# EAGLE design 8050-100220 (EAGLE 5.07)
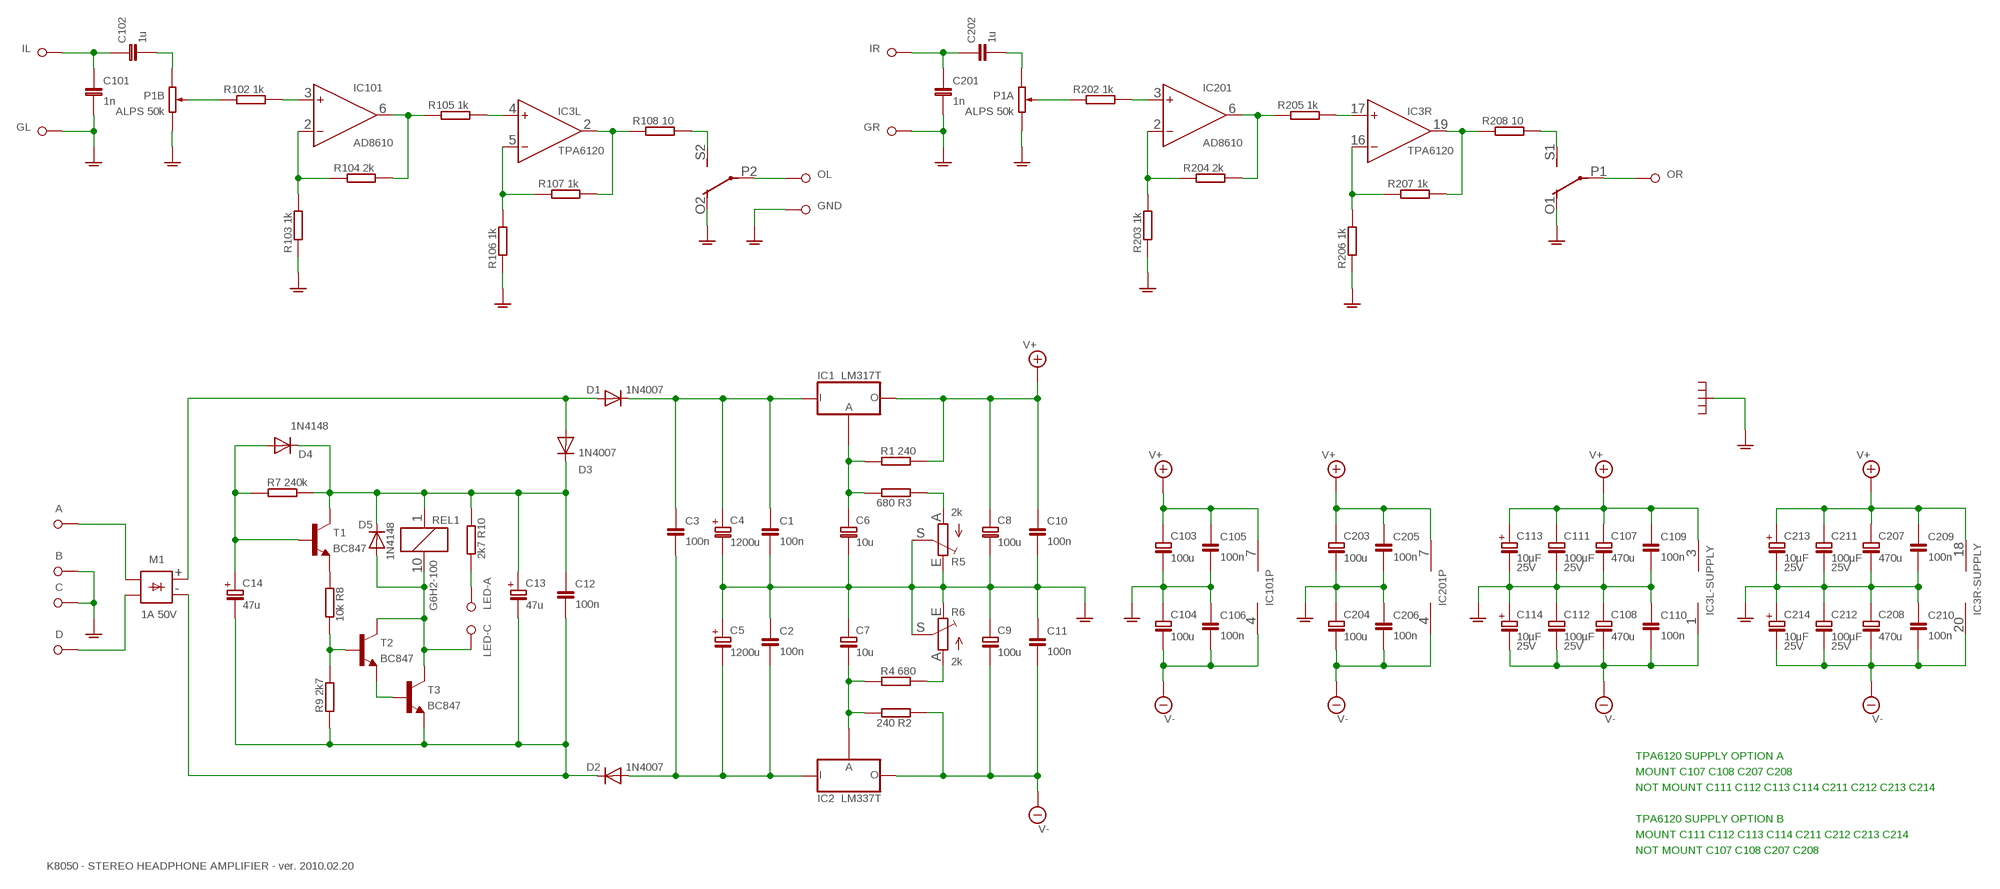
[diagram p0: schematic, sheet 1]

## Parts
A  AC 1  2,15/1,0  [2,15/1,0]
B  AC COM  2,15/1,0  [2,15/1,0]
C  AC COM  2,15/1,0  [2,15/1,0]
C1  100n  C075-042X103  [C075-042X103]
C2  100n  C075-042X103  [C075-042X103]
C3  100n  C075-042X103  [C075-042X103]
C4  1200u  ELECTROLYTIC-FC-E12X30  [E-12-30]
C5  1200u  ELECTROLYTIC-FC-E12X30  [E-12-30]
C6  10u  FM1E470  [E-050-110-020-05]
C7  10u  FM1E470  [E-050-110-020-05]
C8  100u  FM1E101  [E-063-112-025-05]
C9  100u  FM1E101  [E-063-112-025-05]
C10  100n  C075-042X103  [C075-042X103]
C11  100n  C075-042X103  [C075-042X103]
C12  100n  C075-042X103  [C075-042X103]
C13  47u  ELECTROLYTIC-FC-E04X07  [E-04-07]
C14  47u  ELECTROLYTIC-FC-E04X07  [E-04-07]
C101  1n  CC1206  [C1206]
C102  1u  C075-063X106  [C075-063X106]
C103  100u  FM1E101  [E-063-112-025-05]
C104  100u  FM1E101  [E-063-112-025-05]
C105  100n  CC1206  [C1206]
C106  100n  CC1206  [C1206]
C107  470u  FM1E471  [E-100-160-050-06]
C108  470u  FM1E471  [E-100-160-050-06]
C109  100n  CC1206  [C1206]
C110  100n  CC1206  [C1206]
C111  100µF  FM1E101  [E-063-112-025-05]
C112  100µF  FM1E101  [E-063-112-025-05]
C113  10µF  FC1E100  [E-040-070-015-045]
C114  10µF  FC1E100  [E-040-070-015-045]
C201  1n  CC1206  [C1206]
C202  1u  C075-063X106  [C075-063X106]
C203  100u  FM1E101  [E-063-112-025-05]
C204  100u  FM1E101  [E-063-112-025-05]
C205  100n  CC1206  [C1206]
C206  100n  CC1206  [C1206]
C207  470u  FM1E471  [E-100-160-050-06]
C208  470u  FM1E471  [E-100-160-050-06]
C209  100n  CC1206  [C1206]
C210  100n  CC1206  [C1206]
C211  100µF  FM1E101  [E-063-112-025-05]
C212  100µF  FM1E101  [E-063-112-025-05]
C213  10µF  FC1E100  [E-040-070-015-045]
C214  10µF  FC1E100  [E-040-070-015-045]
D  AC 2  2,15/1,0  [2,15/1,0]
D1  1N4007  1N4004  [DO41-10]
D2  1N4007  1N4004  [DO41-10]
D3  1N4007  1N4004  [DO41-10]
D4  1N4148  1N4148DO35-7  [DO35-7]
D5  1N4148  1N4148DO35-7  [DO35-7]
GL  GND  2,15/1,0  [2,15/1,0]
GND  GND1  2,15/1,0  [2,15/1,0]
GR  GND  2,15/1,0  [2,15/1,0]
IC1  LM317T  LM317TS  [317TS]
IC2  LM337T  LM337TS  [337TS]
IC3  TPA6120  [SO20-POWERPAD]
IC101  AD8610  AD811_SO8  [SO8]
IC201  AD8610  AD811_SO8  [SO8]
IL  IN-L  2,15/1,0  [2,15/1,0]
IR  IN-R  2,15/1,0  [2,15/1,0]
LED-A  AC 1  2,15/1,0  [2,15/1,0]
LED-C  AC 1  2,15/1,0  [2,15/1,0]
M1  1A 50V  B40C1500R  [RB1A]
OL  OUT-L  2,15/1,0  [2,15/1,0]
OR  RIGHT OUT  2,15/1,0  [2,15/1,0]
P1  ALPS 50k  POT-DUAL  [ALPS-27]
R1  240  RR1206  [R1206]
R2  240  RR1206  [R1206]
R3  680  RR1206  [R1206]
R4  680  RR1206  [R1206]
R5  2k  TRIM_EU-B64Y  [B64Y]
R6  2k  TRIM_EU-B64Y  [B64Y]
R7  240k  RR1206  [R1206]
R8  10k  RR1206  [R1206]
R9  2k7  RR1206  [R1206]
R10  2k7  RR1206  [R1206]
R102  1k  RR1206  [R1206]
R103  1k  RR1206  [R1206]
R104  2k  RR1206  [R1206]
R105  1k  RR1206  [R1206]
R106  1k  RR1206  [R1206]
R107  1k  RR1206  [R1206]
R108  10  RR1206  [R1206]
R202  1k  RR1206  [R1206]
R203  1k  RR1206  [R1206]
R204  2k  RR1206  [R1206]
R205  1k  RR1206  [R1206]
R206  1k  RR1206  [R1206]
R207  1k  RR1206  [R1206]
R208  10  RR1206  [R1206]
REL1  G6H2-100  [G6H2-100]
T1  BC847  BC847SMD  [SOT23]
T2  BC847  BC847SMD  [SOT23]
T3  BC847  BC847SMD  [SOT23]

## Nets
AGND [GND]: B.1(P) C1.2 C2.1 C4.- C5.+ C6.- C7.+ C8.- C9.+ C10.2 C11.1 C101.2 C103.- C104.+ C105.2 C106.1 C107.- C108.+ C109.2 C110.1 C111.- C112.+ C113.- C114.+ C201.2 C203.- C204.+ C205.2 C206.1 C207.- C208.+ C209.2 C210.1 C211.- C212.+ C213.- C214.+ C.1(P) GL.1(P) GND.1(P) GR.1(P) IC3.THERMAL(THERMAL:THERMAL) P1.R1-A(A:A) P1.R2-A(B:A) R5.E R5.S R6.E R6.S R103.1 R106.1 R203.1 R206.1 REL1.O1(2:O) REL1.O2(3:O)
N$1 [SIGNAL_LO]: C101.1 C102.1 IL.1(P)
N$2 [SIGNAL_LO]: C201.1 C202.1 IR.1(P)
N$3 [SIGNAL_LO]: C202.2 P1.R1-C(A:C)
N$4 [SIGNAL_LO]: C102.2 P1.R2-C(B:C)
N$6 [SIGNAL_LO]: IC201.3(IN+) R202.2
N$7 [SIGNAL_LO]: IC101.2(IN-) R103.2 R104.1
N$8 [SIGNAL_LO]: P1.R1-B(A:B) R202.1
N$9 [POWER]: C1.1 C3.1 C4.+ D1.C IC1.3(IN)
N$10 [SIGNAL_LO]: IC201.2(IN-) R203.2 R204.1
N$11 [SIGNAL_LO]: IC201.6(OUT) R204.2 R205.1
N$12 [SIGNAL_LO]: IC101.6(OUT) R104.2 R105.1
N$13 [SIGNAL_LO]: IC3.4(L:IN+) R105.2
N$14 [SIGNAL_LO]: IC3.5(L:IN-) R106.2 R107.1
N$15 [SIGNAL_LO]: IC3.17(R:IN+) R205.2
N$16 [SIGNAL_LO]: IC3.16(R:IN-) R206.2 R207.1
N$17 [SIGNAL_HI]: IC3.2(L:OUT) R107.2 R108.1
N$18 [SIGNAL_HI]: IC3.19(R:OUT) R207.2 R208.1
N$19 [SIGNAL_HI]: R108.2 REL1.S2(3:S)
N$20 [SIGNAL_HI]: OL.1(P) REL1.P2(3:P)
N$21: R4.2 R6.A
N$23: LED-A.1(P) R10.1
N$24 [POWER]: A.1(P) M1.AC@1(~)
N$25 [POWER]: D.1(P) M1.AC@2(~)
N$26 [POWER]: C7.- IC2.1(ADJ) R2.2 R4.1
N$27 [POWER]: C6.+ IC1.1(ADJ) R1.1 R3.2
N$28 [SIGNAL_HI]: R208.2 REL1.S1(2:S)
N$29 [SIGNAL_HI]: OR.1(P) REL1.P1(2:P)
N$30 [SIGNAL_LO]: P1.R2-B(B:B) R102.1
N$31 [POWER]: C12.2 C13.- C14.- D2.C M1.- R9.1 T3.2(E)
N$32: T2.2(E) T3.1(B)
N$33: R8.2 R9.2 T2.1(B)
N$34 [SIGNAL_LO]: IC101.3(IN+) R102.2
N$35: R8.1 T1.2(E)
N$36: C14.+ D4.A R7.1 T1.1(B)
N$37 [POWER]: C2.2 C3.2 C5.- D2.A IC2.2(IN)
N$38 [POWER]: D1.A D3.A M1.+
N$39: R3.1 R5.A
N$40: D5.A LED-C.1(P) REL1.10 T2.3(C) T3.3(C)
N$42 [POWER]: C12.1 C13.+ D3.C D4.C D5.C R7.2 R10.2 REL1.1 T1.3(C)
V+ [POWER]: C8.+ C10.1 C103.+ C105.1 C107.+ C109.1 C111.+ C113.+ C203.+ C205.1 C207.+ C209.1 C211.+ C213.+ IC1.2(OUT) IC3.3(L-SUPPLY:V+) IC3.18(R-SUPPLY:V+) IC101.7(V+) IC201.7(V+) R1.2
V- [POWER]: C9.- C11.2 C104.- C106.2 C108.- C110.2 C112.- C114.- C204.- C206.2 C208.- C210.2 C212.- C214.- IC2.3(OUT) IC3.1(L-SUPPLY:V-) IC3.20(R-SUPPLY:V-) IC101.4(V-) IC201.4(V-) R2.1
Unconnected: IC101.1(NC) IC101.5(NC) IC101.8(NC) IC201.1(NC) IC201.5(NC) IC201.8(NC)

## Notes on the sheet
- TPA6120 SUPPLY OPTION A
- MOUNT C107 C108 C207 C208
- NOT MOUNT C111 C112 C113 C114 C211 C212 C213 C214
- TPA6120 SUPPLY OPTION B
- MOUNT C111 C112 C113 C114 C211 C212 C213 C214
- NOT MOUNT C107 C108 C207 C208
- K8050 - STEREO HEADPHONE AMPLIFIER - ver. 2010.02.20

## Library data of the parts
A B C D GL GND GR IL IR LED-A LED-C OL OR = wirepad:2,15/1,0: THROUGH-HOLE PAD
C1-C3 C10-C12 C101 C102 C105 C106 C109 C110 C201 C202 C205 C206 C209 C210 = rlc:C: CAPACITOR, European symbol
C4 C5 C13 C14 = capacitors-panasonic:ELECTROLYTIC: Aluminium Electrolytic Capacitor
C6 C7 = capacitors-panasonic-fm-a:FM1E470: 47µF / 25V; VALUE: 47µF; VOLTAGE: 25V
C8 C9 C103 C104 C203 C204 = capacitors-panasonic-fm-a:FM1E101: 100µF / 25V; VALUE: 100µF; VOLTAGE: 25V
C107 C108 C207 C208 = capacitors-panasonic-fm-a:FM1E471: 470µF / 25V; VALUE: 470µF; VOLTAGE: 25V
C111 C112 C211 C212 = capacitors-panasonic-fm-a:FM1E101: 100µF / 25V; VOLTAGE: 25V
C113 C114 C213 C214 = Panasonic - FC - A:FC1E100: 10µF / 25V; VOLTAGE: 25V
D1-D3 = diode:1N4004: DIODE
D4 D5 = diode:1N4148: DIODE
IC1 = lm3x7:LM317TS: VOLTAGE REGULATOR
IC2 = lm3x7:LM337TS: VOLTAGE REGULATOR
IC3 = ic-linear-texasinstruments:TPA6120
IC101 IC201 = analog-devices:AD811_SO8: ANALOG DEVICES
M1 = rectifiers:B40C1500R
P1 = rlc:POT-DUAL
R1-R4 R7-R10 R102-R108 R202-R208 = rlc:R: RESISTOR, European symbol
R5 R6 = pot:TRIM_EU-: POTENTIOMETER
REL1 = relay:G6H2-100: RELAY 2 x switch, 0.5 A/125 V AC, 1 A/30 V DC, Omron
T1-T3 = transistor-npn:BC847*: NPN Transistor

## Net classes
0 SMD: width 0.305 mm, clearance 0.254 mm
1 SIGNAL_LO: width 0.305 mm, clearance 0.406 mm
2 SIGNAL_HI: width 0.61 mm, clearance 0.914 mm
3 POWER: width 0.61 mm, clearance 0.61 mm
7 GND: clearance 0.61 mm

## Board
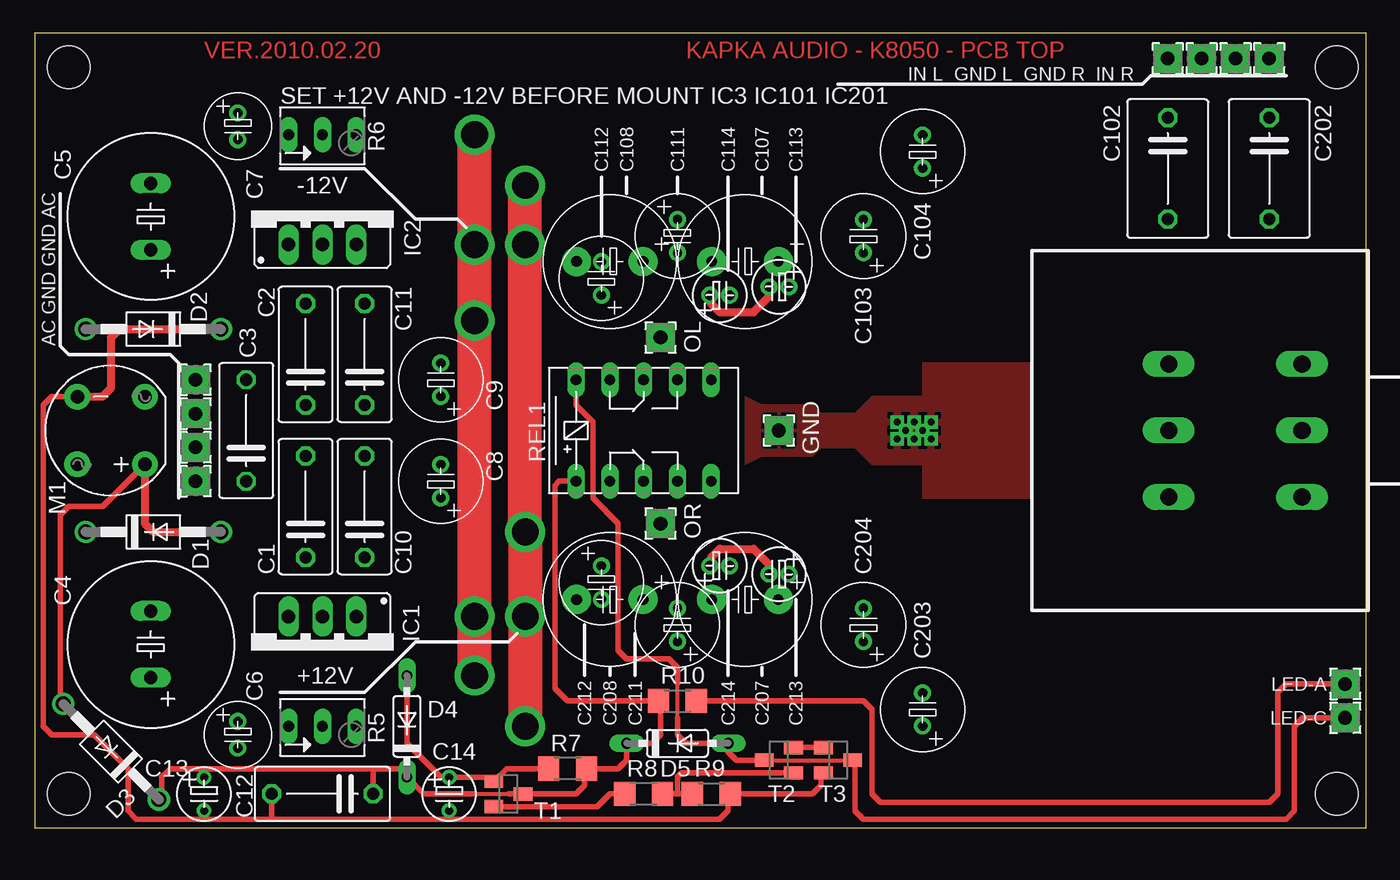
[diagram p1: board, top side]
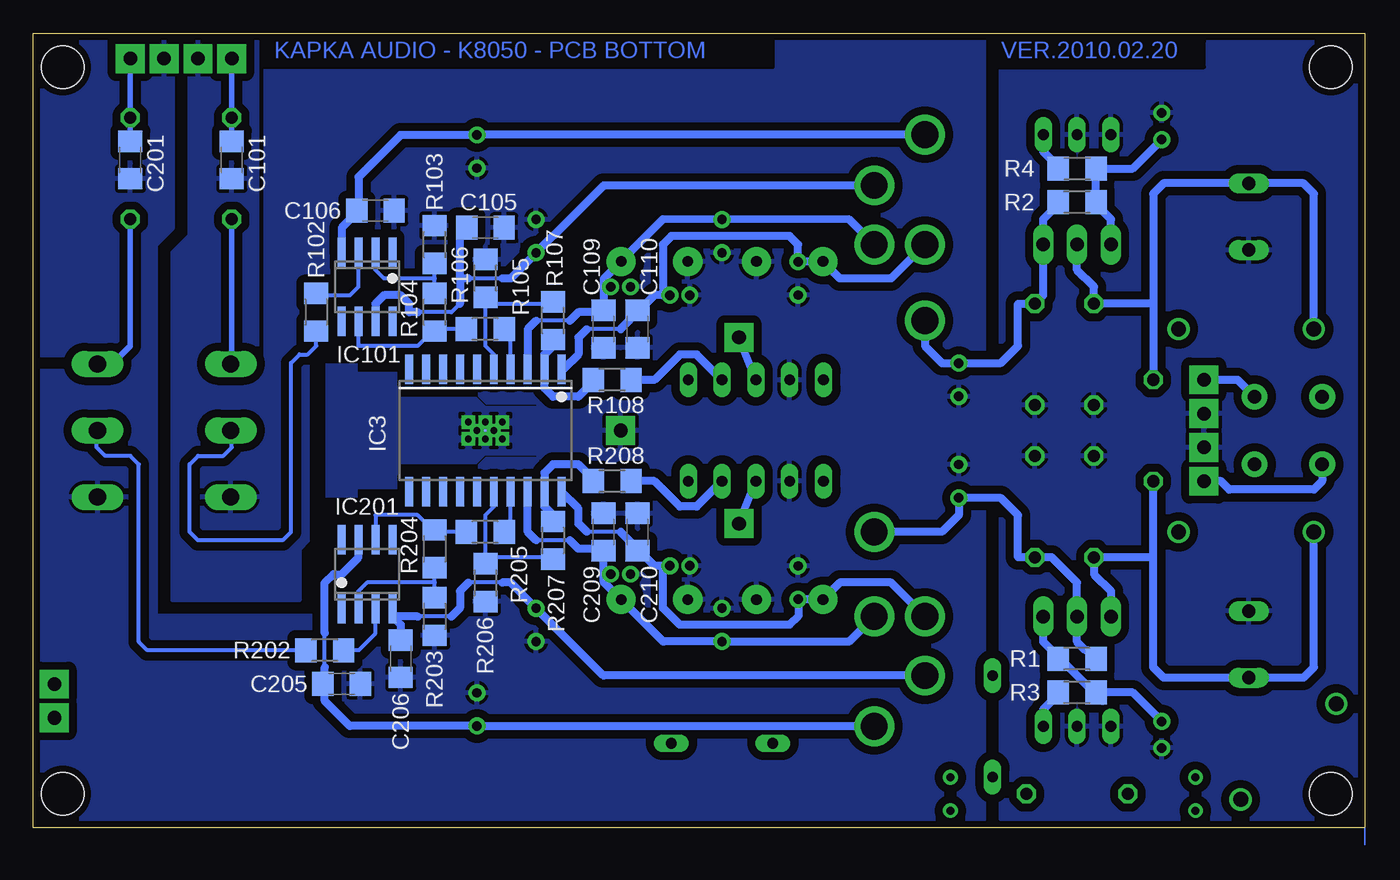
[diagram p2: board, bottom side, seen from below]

Size 100 x 59.69 mm. Coordinates in mm from the lower left corner, seen from the top.
Outline: 0,0 100,0 100,59.69 0,59.69 0,0
Copper layers (1*16): Top 0.035mm / dielectric 1.5mm / Bottom 0.035mm
Design rules "satland": minimum track width 10mil, minimum drill 0.3mm, track to track 10mil, track to pad 10mil, pad to pad 10mil, via to via 10mil, smd to smd 10mil, copper to edge 20mil, drill to drill 10mil, minimum pad ring 10mil, minimum via ring 10mil, stop-mask expansion 0mil, vias tented up to drill 0mil, thermal gap 10mil
Holes 3.2 mm at 97.79,57.15 97.79,2.54 2.54,2.54 2.54,57.15
tRestrict: 4 lines
bRestrict: 19 lines

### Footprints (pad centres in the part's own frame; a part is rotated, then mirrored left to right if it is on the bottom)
2,15/1,0 = drill 1.016 pad 2.159 square: 1 0,0
C075-042X103 = drill 0.914 octagon: 1 -3.81,0; 2 3.81,0
E-12-30 = drill 1 long: + -2.5,0; - 2.5,0
E-050-110-020-05 = drill 0.7 pad 1.27 round: + -1,0; - 1,0
E-063-112-025-05 = drill 0.7 pad 1.27 round: + -1.25,0; - 1.25,0
E-04-07 = drill 0.6 round: + -1.25,0; - 1.25,0
C1206 = smd 1.6 x 1.8: 1 -1.4,0; 2 1.4,0
C075-063X106 = drill 0.914 octagon: 1 -3.81,0; 2 3.81,0
E-100-160-050-06 = drill 0.8 pad 2.184 round: + -2.5,0; - 2.5,0
E-040-070-015-045 = drill 0.7 pad 1.27 round: + -0.75,0; - 0.75,0
DO41-10 = drill 1.118 round: A 5.08,0; C -5.08,0
DO35-7 = drill 0.813 long: A 3.81,0; C -3.81,0
317TS = drill 1.016 long: 1 -2.54,-2.54; 2 0,-2.54; 3 2.54,-2.54
337TS = drill 1.016 long: 1 -2.54,-2.54; 2 0,-2.54; 3 2.54,-2.54
SO20-POWERPAD = smd 0.6 x 2.2: 1 -5.715,-4.6; 2 -4.445,-4.6; 3 -3.175,-4.6; 4 -1.905,-4.6; 5 -0.635,-4.6; 6 0.635,-4.6; 7 1.905,-4.6; 8 3.175,-4.6; 9 4.445,-4.6; 10 5.715,-4.6; 11 5.715,4.6; 12 4.445,4.6; 13 3.175,4.6; 14 1.905,4.6; 15 0.635,4.6; 16 -0.635,4.6; 17 -1.905,4.6; 18 -3.175,4.6; 19 -4.445,4.6; 20 -5.715,4.6 | smd 0.635 x 0.254: THERMAL 0,0
SO8 = smd 0.6 x 2.2: 1 -1.905,-2.6; 2 -0.635,-2.6; 3 0.635,-2.6; 4 1.905,-2.6; 5 1.905,2.6; 6 0.635,2.6; 7 -0.635,2.6; 8 -1.905,2.6
RB1A = drill 1.016 pad 1.93 round: + -2.54,2.54; - 2.54,-2.54; AC@1 2.54,2.54; AC@2 -2.54,-2.54
ALPS-27 = drill 1.3 long: R1-A -5,-5; R1-B 0,-5; R1-C 5,-5; R2-A -5,5; R2-B 0,5; R2-C 5,5
R1206 = smd 1.6 x 1.803: 1 -1.422,0; 2 1.422,0
B64Y = drill 0.813 long: A 2.54,0; E -2.54,0; S 0,0
G6H2-100 = drill 0.813 long: 1 -5.08,-3.81; 5 5.08,-3.81; 6 5.08,3.81; 10 -5.08,3.81; O1 -2.54,-3.81; O2 -2.54,3.81; P1 0,-3.81; P2 0,3.81; S1 2.54,-3.81; S2 2.54,3.81
SOT23 = smd 1 x 1.4: 1 -0.95,-1.1; 2 0.95,-1.1; 3 0,1.1

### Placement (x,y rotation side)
A  12.06,26.04 0 top
B  12.06,31.11 0 top
C  12.06,28.57 0 top
C1  20.32,24.13 90 top
C2  20.32,35.56 90 top
C3  15.88,29.84 90 top
C4  8.7,13.78 90 top
C5  8.7,45.92 90 top
C6  15.24,6.99 270 top
C7  15.24,52.7 270 top
C8  30.48,26.04 90 top
C9  30.48,33.66 90 top
C10  24.77,24.13 90 top
C11  24.77,35.56 90 top
C12  21.59,2.54 180 top
C13  12.7,2.54 270 top
C14  31.11,2.54 270 top
C101  85.09,50.16 270 bottom
C102  85.09,49.53 270 top
C103  62.23,44.45 90 top
C104  66.67,50.8 90 top
C105  66.04,45.09 0 bottom
C106  74.3,46.35 180 bottom
C107  53.34,42.55 180 top
C108  43.18,42.55 180 top
C109  57.15,37.47 270 bottom
C110  54.61,37.47 90 bottom
C111  48.26,44.45 270 top
C112  42.55,41.27 90 top
C113  55.88,40.64 180 top
C114  51.44,40.01 0 top
C201  92.71,50.16 270 bottom
C202  92.71,49.53 270 top
C203  66.67,8.89 90 top
C204  62.23,15.24 90 top
C205  76.83,10.79 0 bottom
C206  72.39,12.7 90 bottom
C207  53.34,17.14 180 top
C208  43.18,17.14 180 top
C209  57.15,22.23 90 bottom
C210  54.61,22.23 270 bottom
C211  48.26,15.24 90 top
C212  42.55,18.41 270 top
C213  55.88,19.05 180 top
C214  51.44,19.68 0 top
D  12.06,33.66 0 top
D1  8.89,22.23 0 top
D2  8.89,37.47 180 top
D3  5.71,5.71 135 top
D4  27.94,7.62 90 top
D5  48.26,6.35 0 top
GL  87.63,57.78 90 top
GND  55.88,29.84 90 top
GR  90.17,57.78 90 top
IC1  21.59,13.34 180 top
IC2  21.59,46.35 0 top
IC3  66.04,29.84 180 bottom
IC101  74.93,40.64 180 bottom
IC201  74.93,19.05 0 bottom
IL  85.09,57.78 90 top
IR  92.71,57.78 90 top
LED-A  98.42,10.79 0 top
LED-C  98.42,8.26 0 top
M1  5.71,29.84 180 top
OL  46.99,36.83 90 top
OR  46.99,22.86 90 top
P1  90.17,29.84 90 top
R1  21.59,12.7 0 bottom
R2  21.59,46.99 0 bottom
R3  21.59,10.16 0 bottom
R4  21.59,49.53 180 bottom
R5  21.59,7.62 0 top
R6  21.59,52.07 0 top
R7  40.01,4.45 0 top
R8  45.72,2.54 0 top
R9  50.8,2.54 180 top
R10  48.26,9.53 180 top
R102  78.74,38.73 90 bottom
R103  69.85,43.81 270 bottom
R104  69.85,38.73 270 bottom
R105  66.04,37.47 0 bottom
R106  66.04,41.27 270 bottom
R107  60.96,38.1 270 bottom
R108  56.52,33.66 0 bottom
R202  78.11,13.34 0 bottom
R203  69.85,15.88 90 bottom
R204  69.85,20.95 90 bottom
R205  66.04,22.23 0 bottom
R206  66.04,18.41 90 bottom
R207  60.96,21.59 90 bottom
R208  56.52,26.04 0 bottom
REL1  45.72,29.84 0 top
T1  35.56,2.54 270 top
T2  55.88,5.08 90 top
T3  60.33,5.08 270 top

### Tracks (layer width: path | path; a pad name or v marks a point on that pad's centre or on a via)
AGND  (via drill 0.5 pad 0.81)
  Top 0.61: C213.- 55.13,19.8 53.98,20.95 51.44,20.95 50.8,20.32 50.8,19.8 C214.+ | C113.- 55.13,39.89 53.98,38.73 51.44,38.73 50.8,39.37 50.8,39.89 C114.+
  other vias: 65.41,29.84 64.77,30.48 64.77,29.21 66.04,29.21 67.31,29.21 66.04,30.48 67.31,30.48 66.67,29.84
  pour Top: 53.34,32.38 53.34,27.3 54.61,27.94 58.42,27.94 59.05,28.57 61.59,28.57 62.87,27.3 66.67,27.3 66.67,24.77 74.93,24.77 74.93,34.92 66.67,34.92 66.67,32.38 62.87,32.38 61.59,31.11 59.05,31.11 58.42,31.75 54.61,31.75
  pour Bottom: 0.64,0.64 0.64,59.05 27.3,59.05 27.3,35.56 28.57,35.56 28.57,59.05 82.55,59.05 82.55,34.92 84.45,34.92 84.45,35.56 83.19,35.56 83.19,59.05 88.27,59.05 88.27,44.45 89.53,43.18 89.53,17.14 80.01,17.14 80.01,20.95 79.38,21.59 79.38,36.2 78.11,36.2 78.11,20.95 78.74,20.32 78.74,15.88 90.81,15.88 90.81,43.81 89.53,45.09 89.53,59.05 99.69,59.05 99.69,35.56 97.16,35.56 97.16,34.29 99.69,34.29 99.69,0.64 28.57,0.64 28.57,24.13 27.3,24.13 27.3,0.64
N$1
  Bottom 0.406: IL.1 C102.1 C101.1
N$2
  Bottom 0.406: IR.1 C202.1 C201.1
N$3
  Bottom 0.406: C202.2 92.71,36.2 93.98,34.92 95.09,34.92 P1.R1-C
N$4
  Bottom 0.406: C102.2 85.09,34.92 P1.R2-C
N$6
  Bottom 0.305: IC201.3 74.3,14.61 75.56,13.34 R202.2
N$7
  Bottom 0.305: R104.1 69.85,41.27 | 69.85,41.27 R103.2 | IC101.2 74.3,41.91 73.66,41.27 69.85,41.27
N$8
  Bottom 0.305: R202.1 91.44,13.34 92.08,13.97 92.08,27.3 92.71,27.94 94.61,27.94 95.25,28.57 95.25,29.77 P1.R1-B
N$9
  Bottom 0.61: 15.88,20.32 C3.1 | 15.88,20.32 C1.1 20.32,19.05 19.05,17.78 IC1.3 | D1.C 3.81,12.06 4.6,11.28 C4.+ 15.09,11.28 15.88,12.06 15.88,20.32
N$10
  Bottom 0.305: IC201.2 75.56,17.78 74.93,18.41 69.85,18.41 | R203.2 69.85,18.41 | 69.85,18.41 R204.1
N$11
  Bottom 0.305: R205.1 69.22,22.23 69.37,22.38 R204.2 70,22.38 71.12,23.5 74.3,23.5 IC201.6
N$12
  Bottom 0.305: R105.1 69.7,37.47 R104.2 70,37.31 71.12,36.2 75.56,36.2 IC101.6
N$13
  Bottom 0.305: R105.2 64.14,36.98 IC3.4
N$14
  Bottom 0.305: R107.1 61.44,39.52 61.59,39.37 65.56,39.37 R106.2 66.04,36.2 65.41,35.56 IC3.5
N$15
  Bottom 0.305: IC3.17 64.14,22.86 64.62,22.38 R205.2
N$16
  Bottom 0.305: R207.1 61.11,20.32 65.41,20.32 65.89,19.84 R206.2 66.04,23.5 65.41,24.13 IC3.16
N$17
  Bottom 0.61: R108.1 58.42,33.17 58.42,33.02 59.05,32.38 60.96,32.38 61.59,33.02 IC3.2 61.59,35.56 60.96,36.2 R107.2
N$18
  Bottom 0.61: R208.1 58.42,26.52 58.42,26.67 59.05,27.3 60.96,27.3 61.59,26.67 IC3.19 61.59,24.13 60.96,23.5 R207.2
N$19
  Bottom 0.61: R108.2 53.34,33.66 51.44,35.56 50.16,35.56 REL1.S2
N$20
  Bottom 0.61: REL1.P2 OL.1
N$21
  Bottom 0.61: R6.A 24.13,50.8 23.5,50.16 23.5,50.01 R4.2
N$22
  Bottom 0.127: 0,0 0,-1.27
N$23
  Top 0.406: LED-A.1 93.98,10.79 93.34,10.16 93.34,2.54 92.71,1.91 63.5,1.91 62.87,2.54 62.87,8.89 62.23,9.53 R10.1
N$24
  Bottom 0.61: M1.AC@1 3.17,26.04 3.81,25.4 10.16,25.4 10.79,26.04 A.1
N$25
  Bottom 0.61: M1.AC@2 9.53,33.66 D.1
N$26
  Bottom 0.61: IC2.1 19.05,45.72 19.68,46.35 19.68,46.51 R2.2 R4.1 17.41,49.53 C7.-
N$27
  Bottom 0.61: IC1.1 24.13,13.97 23.5,13.34 23.5,13.18 R1.1 22.86,12.7 19.68,9.53 19.68,9.68 R3.2 17.41,10.16 C6.+
N$28
  Bottom 0.61: R208.2 53.34,26.04 51.44,24.13 50.16,24.13 REL1.S1
N$29
  Bottom 0.61: OR.1 REL1.P1
N$30
  Bottom 0.305: P1.R2-B 85.09,29.77 85.09,28.57 85.72,27.94 87.63,27.94 88.27,27.3 88.27,22.23 87.63,21.59 81.28,21.59 80.64,22.23 80.64,34.92 80.01,35.56 79.38,35.56 78.74,36.2 R102.1
N$31
  Top 0.406: M1.- 1.27,32.38 0.64,31.75 0.64,7.62 1.27,6.99 4.45,6.99 6.99,4.45 6.99,1.27 7.62,0.64 12.7,0.64 | 12.7,0.64 C13.- | 12.7,0.64 17.78,0.64 | 17.78,0.64 C12.2 | T3.2 59.05,3.96 59.05,3.17 58.42,2.54 R9.1 52.07,2.39 52.07,1.27 51.44,0.64 31.11,0.64 | 17.78,0.64 31.11,0.64 | 31.11,0.64 C14.-
  Top 0.61: D2.C 6.35,37.47 5.71,36.83 5.71,33.02 5.08,32.38 M1.-
N$32
  Top 0.406: T2.2 T3.1
N$33
  Top 0.406: R8.2 48.26,2.54 | 48.26,2.54 R9.2 | T2.1 48.58,4.13 48.26,3.81 48.26,2.54
N$34
  Bottom 0.305: IC101.3 75.56,40.64 76.2,40.01 78.59,40.01 R102.2
N$35
  Top 0.406: T1.2 42.23,1.59 43.18,2.54 R8.1
N$36
  Top 0.406: T1.1 34.16,3.79 C14.+ 31.09,3.81 30.48,3.81 27.96,6.33 27.94,6.33 D4.A | T1.1 34.92,3.49 34.92,3.81 | R7.1 35.41,4.45 T1.1
N$37
  Bottom 0.61: 15.88,39.37 C3.2 | 15.88,39.37 C2.2 20.32,40.64 21.59,41.91 IC2.2 | D2.A 3.81,47.62 4.6,48.41 C5.- 15.09,48.41 15.88,47.62 15.88,39.37
N$38
  Top 0.406: D3.A 1.91,9.53 1.91,23.5 2.54,24.13 5.08,24.13 M1.+
  Top 0.61: D1.A 8.89,22.23 8.26,22.86 M1.+
N$39
  Bottom 0.61: R5.A 24.13,8.89 23.01,10.01 R3.1
N$40
  Top 0.305: 48.26,8.26 48.26,10.79 | T2.3 T3.3
  Top 0.406: 48.26,10.79 48.26,12.06 47.62,12.7 44.45,12.7 43.81,13.34 43.81,22.86 41.91,24.77 41.91,30.48 40.64,31.75 REL1.10 | 48.26,8.26 48.26,6.99 48.9,6.35 D5.A 52.07,5.71 52.7,5.08 T2.3 | T3.3 61.59,4.91 61.59,1.27 62.23,0.64 93.98,0.64 94.61,1.27 94.61,7.62 95.25,8.26 LED-C.1
N$42
  Top 0.305: 33.02,2.54 35.56,2.54
  Top 0.406: 35.56,2.54 T1.3 40.64,2.54 41.27,3.17 41.27,4.29 R7.2 43.81,4.45 44.45,5.08 D5.C 46.35,6.35 46.99,6.99 46.99,9.37 R10.2 40.01,9.53 39.05,10.48 39.05,25.72 39.37,26.04 REL1.1 | 12.7,4.45 10.16,4.45 9.53,3.81 9.53,2.34 D3.C | 12.7,4.45 C13.+ | 12.7,4.45 25.4,4.45 | 25.4,4.45 27.3,4.45 D4.C 29.21,2.54 33.02,2.54 | 25.4,4.45 C12.1
V+  (via drill 2)
  Top 2.54: v36.83,7.62 v36.83,15.88 v36.83,22.23 v36.83,43.81 v36.83,48.26
  Bottom 0.305: 78.11,12.06 78.11,14.61 | 59.69,21.59 62.23,21.59 | 59.69,38.1 62.23,38.1 | 64.77,41.27 67.31,41.27 | 71.12,38.73 68.58,38.73 67.94,39.37
  Bottom 0.61: v36.83,48.26 57.15,48.26 60.96,44.45 60.98,44.45 C103.+ 62.23,43.18 64.14,41.27 64.77,41.27 | v36.83,7.62 66.66,7.62 C203.+ 76.22,7.64 78.11,9.53 78.11,10.66 C205.1 | C205.1 78.23,10.31 | C107.+ 55.88,42.51 55.92,42.51 | C107.+ 55.88,42.55 52.7,45.72 C111.+ 38.73,45.72 v36.83,43.81 | C205.1 78.11,10.93 78.11,12.06 | IC201.7 75.56,20.32 76.83,19.05 77.47,19.05 78.11,18.41 78.11,14.61 | IC3.18 62.87,22.23 62.23,21.59 | 59.69,21.59 59.05,20.95 57.78,20.95 57.66,20.82 C209.1 57.15,18.45 | IC3.3 62.87,37.47 62.23,38.1 | 59.69,38.1 59.05,38.73 57.28,38.73 C109.1 57.15,41.23 | C107.+ 57.15,41.23 | 57.15,18.45 C207.+ 52.66,13.97 52.65,13.99 C211.+ 48.24,13.97 38.73,13.97 v36.83,15.88 | 67.31,41.27 67.94,41.27 | 67.94,41.27 67.94,44.58 C105.1 | 71.12,38.73 71.75,38.73 71.75,39.37 72.39,40.01 73.66,40.01 74.3,39.37 IC101.7 | 67.94,41.27 67.94,39.37 | v36.83,22.23 31.75,22.23 30.48,23.5 C8.+ 30.46,24.77 27.3,24.77 26.04,23.5 26.04,20.32 C10.1 23.5,20.32 21.59,18.41 IC1.2 21.59,13.97 20.95,13.34 20.8,13.34 R1.2 | C113.+ 56.63,40.72 57.15,41.23 | C213.+ 56.63,18.98 57.15,18.45
V-  (via drill 2)
  Top 2.54: v33.02,11.43 v33.02,15.88 v33.02,38.1 v33.02,43.81 v33.02,52.07
  Bottom 0.305: 64.77,18.41 67.31,18.41 | 68.58,15.88 71.12,15.88 | 55.88,22.23 58.42,22.23 | 55.88,37.47 58.42,37.47
  Bottom 0.61: v33.02,38.1 33.02,36.2 31.73,34.91 C9.- 30.46,34.92 27.3,34.92 26.04,36.2 26.04,39.37 C11.2 24.13,40.01 IC2.3 24.13,45.72 23.5,46.35 23.5,46.51 R2.1 | v33.02,43.81 35.56,41.27 39.41,41.27 C108.- 42.52,42.55 C112.- 42.55,43.81 43.18,44.45 52.07,44.45 52.7,43.81 52.7,40.01 | v33.02,11.43 57.15,11.43 57.15,11.45 57.19,11.45 C204.- 64.16,18.41 64.77,18.41 | 33.04,52.05 v33.02,52.07 66.66,52.07 C104.- 72.41,52.05 75.56,48.9 75.56,46.99 75.69,46.86 C106.2 76.2,45.85 76.2,45.72 76.83,45.09 IC101.4 | 67.31,18.41 67.94,17.78 67.94,16.51 68.58,15.88 | 71.12,15.88 73.03,15.88 | 73.03,15.88 IC201.4 | 73.03,15.88 72.39,15.24 C206.2 | IC3.20 59.05,23.98 59.05,22.86 58.42,22.23 | 55.88,22.23 54.61,20.95 C210.2 54.48,20.82 53.34,19.68 52.7,19.68 | IC3.1 60.17,34.45 59.05,35.56 59.05,36.83 58.42,37.47 | 55.88,37.47 55.24,38.1 55.24,38.23 C110.2 54.48,38.87 53.34,40.01 52.7,40.01 | v33.02,15.88 35.56,18.41 39.41,18.41 39.41,18.39 39.43,18.39 C208.- 42.52,17.14 | 52.7,19.68 C214.- | 52.7,40.01 C114.- | 52.7,19.68 52.7,16.51 51.44,15.24 43.18,15.24 42.52,15.89 42.52,17.14 | 42.52,17.14 C212.-

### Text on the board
Top: VER.2010.02.20 | KAPKA AUDIO - K8050 - PCB TOP
Bottom: VER.2010.02.20 | KAPKA AUDIO - K8050 - PCB BOTTOM
tPlace: IN L GND L GND R IN R | -12V | AC GND GND AC | +12V
tNames: SET +12V AND -12V BEFORE MOUNT IC3 IC101 IC201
